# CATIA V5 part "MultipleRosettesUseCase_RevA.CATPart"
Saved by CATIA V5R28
Part number: MultipleRosettesUseCase
Bounding box of the stored display mesh (mm): x -1574.8 to 2336.8, y -564.133 to 564.133, z 0 to 0
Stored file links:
  \\A5978449\c$\Users\jvl2147\Documents\AP242 testing\MultipleRosettesUseCase_RevA.CATPart
  C:\Program Files\Dassault Systemes\B28SP4PRALL\win_b64\startup\composites\CompositesCatalog.CATMaterial
  C:\Program Files\Dassault Systemes\B28SP4PRALL\win_b64\startup\composites\LaminateColors.txt
  C:\Program Files\Dassault Systemes\B28SP4PRALL\win_b64\startup\composites\DropOffPattern1Backslash.txt
  C:\Program Files\Dassault Systemes\B28SP4PRALL\win_b64\startup\composites\DropOffPattern1InverseV.txt
  C:\Program Files\Dassault Systemes\B28SP4PRALL\win_b64\startup\composites\DropOffPattern1InverseV_2Consecutive.txt
  C:\Program Files\Dassault Systemes\B28SP4PRALL\win_b64\startup\composites\DropOffPattern1InverseV_Symmetry.txt
  C:\Program Files\Dassault Systemes\B28SP4PRALL\win_b64\startup\composites\DropOffPattern1InverseW.txt
  C:\Program Files\Dassault Systemes\B28SP4PRALL\win_b64\startup\composites\DropOffPattern1Slash.txt
  C:\Program Files\Dassault Systemes\B28SP4PRALL\win_b64\startup\composites\DropOffPattern1V.txt
  C:\Program Files\Dassault Systemes\B28SP4PRALL\win_b64\startup\composites\DropOffPattern1V_2Consecutive.txt
  C:\Program Files\Dassault Systemes\B28SP4PRALL\win_b64\startup\composites\DropOffPattern1V_Symetry.txt
  C:\Program Files\Dassault Systemes\B28SP4PRALL\win_b64\startup\composites\DropOffPattern1V_Symetry_2Consecutive.txt
  C:\Program Files\Dassault Systemes\B28SP4PRALL\win_b64\startup\composites\DropOffPattern1W.txt
  C:\Program Files\Dassault Systemes\B28SP4PRALL\win_b64\startup\composites\DropOffPattern2Cross.txt
  C:\Program Files\Dassault Systemes\B28SP4PRALL\win_b64\startup\composites\DropOffPattern2Diamond.txt
  C:\Program Files\Dassault Systemes\B28SP4PRALL\win_b64\startup\composites\DropOffPattern2Socks.txt
  C:\Program Files\Dassault Systemes\B28SP4PRALL\win_b64\startup\composites\DropOffPattern45AfterOthers.txt
  C:\Program Files\Dassault Systemes\B28SP4PRALL\win_b64\startup\composites\DropOffPattern4TwinDiamonds45.txt
  C:\Program Files\Dassault Systemes\B28SP4PRALL\win_b64\startup\composites\DropOffPattern5Cross_Pseudo_Sym.txt
  C:\Program Files\Dassault Systemes\B28SP4PRALL\win_b64\startup\composites\DropOffPattern5Diamond_Pseudo_Sym.txt
  C:\Program Files\Dassault Systemes\B28SP4PRALL\win_b64\startup\composites\DropOffPattern5Socks_Pseudo_Sym.txt
  \\A5978449\c$\Users\jvl2147\Documents\AP242 testing\MultipleRosettesUseCase_Export.xlsx
  \\A5978449\c$\Users\jvl2147\Documents\AP242 testing\MSS_MultiRosette.xlsx
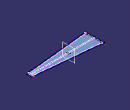
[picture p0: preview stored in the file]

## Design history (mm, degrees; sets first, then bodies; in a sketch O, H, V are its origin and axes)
AxisSystem1: origin (0, 0, 0), X (1, 0, 0), Y (0, 1, 0), Z (0, 0, 1)
AxisSystem2: origin (-1524, 508, 0), X (0.995, -0.0995, 0), Y (0.0995, 0.995, 0), Z (0, 0, 1)
AxisSystem3: origin (-1524, -508, 0), X (0.995, 0.0995, 0), Y (-0.0995, 0.995, 0), Z (0, 0, 1)
CompParametersFeature1 "CATCoParametersFeatName": Value 0, Value 45, Value -45, Value 90, Orientations 0, Orientations 0, Orientations 0
CompGridRoot1
CompStacking1 "Stacking"
Set1 "Construction Geometry"
  Sketch1 on xy-plane, origin (0, 0, 0), H (1, 0, 0), V (0, 1, 0)
    point P1 (-1524, 508)
    line L1 (-1524, 508) -> (2286, 127)
    line L2 (2286, 127) -> (2286, -127)
    line L3 (2286, -127) -> (-1524, -508)
    line L4 (-1524, -508) -> (-1524, 508)
    point P2 (2286, 127)
    point P3 (2286, -127)
    point P4 (-1524, -508)
    distance H P1 = 508
    distance H P4 = 508
    distance H P2 = 127
    distance H P3 = 127
    distance V L4 = 1524
    distance V L2 = 2286
    vertical: L2 V, L4 V
  Set2 "Grid SRE Contstruction"
    Plane1: type Offset, RefPlane ZX plane of AxisSystem2, Offset 25.4, reversed
    Plane2: type Offset, RefPlane ZX plane of AxisSystem3, Offset 25.4
    Plane3: type Offset, RefPlane yz-plane, Offset 1498.6, reversed
    Plane4: type Offset, RefPlane yz-plane, Offset 2260.6
    Plane5: type Offset, RefPlane Plane1, Offset 50.8
    Plane6: type Offset, RefPlane Plane2, Offset 50.8, reversed
    Plane7: type Offset, RefPlane zx-plane, Offset 25.4
    Plane8: type Offset, RefPlane zx-plane, Offset 25.4, reversed
  Fill1: Boundary Sketch1
  Extrapol1: Support Fill1, ExtrapolationElements ({extrapolextrapolationelements ToExtrapol Sketch1, Length 50.8}; {extrapolextrapolationelements Length 0})
Set3 "Engineering Geometry"
  Join1 "Definition Surface": Elements Extrapol1
  Intersect1 "0° Guide Curve 3": ToIntersect1 Extrapol1, ToIntersect2 ZX plane of AxisSystem3
  Intersect2 "0° Guide Curve 1": ToIntersect1 Extrapol1, ToIntersect2 ZX plane of AxisSystem2
  Intersect3 "0° Guide Curve 2": ToIntersect1 ZX plane of AxisSystem1, ToIntersect2 Join1
Body1 (main body)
